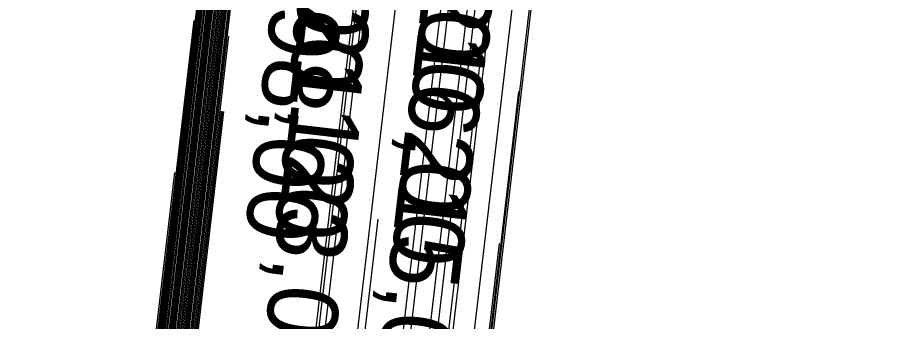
# Model space of a CAD drawing. Extents: x -500397 to -496810, y -1135552 to -1132176.
# Drawn here: x -500397.08 to -500372.54, y -1134717.01 to -1134708.35 of the extents above; entities that cross this region are included whole.
import ezdxf

# ---------------------------------------------------------------- set-up
doc = ezdxf.new("R2010")
doc.units = 0
doc.layers.add('30', color=7, linetype='Continuous')
doc.layers.add('40', color=7, linetype='Continuous')

msp = doc.modelspace()

# ---------------------------------------------------------------- linework, layer by layer
at = {"layer": '30'}
for points in [[(-500387.172, -1134737.454), (-500331.085, -1134256.995)], [(-500332.225, -1134267.69), (-500387.044, -1134737.277)], [(-500387.816, -1134738.339), (-500334.109, -1134278.277)], [(-500335.604, -1134301.879), (-500386.314, -1134736.273)], [(-500387.558, -1134737.985), (-500355.567, -1134463.937)], [(-500387.425, -1134728.512), (-500367.626, -1134558.908)], [(-500388.342, -1134738.221), (-500372.962, -1134606.474)], [(-500386.129, -1134660.947), (-500396.569, -1134750.38), (-500396.567, -1134750.485), (-500396.533, -1134750.568), (-500396.468, -1134750.631), (-500396.372, -1134750.671), (-500395.924, -1134750.792), (-500395.814, -1134750.827), (-500395.707, -1134750.87), (-500395.605, -1134750.921), (-500395.506, -1134750.981), (-500395.106, -1134751.248), (-500395.007, -1134751.313), (-500394.907, -1134751.376), (-500394.805, -1134751.438), (-500394.703, -1134751.498), (-500393.349, -1134752.284), (-500393.183, -1134752.384), (-500393.021, -1134752.487), (-500392.863, -1134752.596), (-500392.707, -1134752.709), (-500392.09, -1134753.172)], [(-500386.669, -1134665.264), (-500396.612, -1134750.439), (-500396.61, -1134750.539), (-500396.578, -1134750.619), (-500396.516, -1134750.678), (-500396.424, -1134750.717), (-500395.997, -1134750.832), (-500395.892, -1134750.864), (-500395.791, -1134750.905), (-500395.694, -1134750.954), (-500395.6, -1134751.012), (-500395.219, -1134751.265), (-500395.124, -1134751.327), (-500395.029, -1134751.388), (-500394.932, -1134751.447), (-500394.835, -1134751.504), (-500393.545, -1134752.253), (-500393.388, -1134752.347), (-500393.233, -1134752.446), (-500393.082, -1134752.55), (-500392.934, -1134752.657), (-500392.346, -1134753.098)], [(-500387.209, -1134669.582), (-500396.655, -1134750.499), (-500396.653, -1134750.593), (-500396.622, -1134750.669), (-500396.564, -1134750.725), (-500396.476, -1134750.762), (-500396.071, -1134750.871), (-500395.971, -1134750.902), (-500395.875, -1134750.941), (-500395.783, -1134750.988), (-500395.693, -1134751.042), (-500395.331, -1134751.283), (-500395.241, -1134751.342), (-500395.151, -1134751.399), (-500395.059, -1134751.455), (-500394.966, -1134751.51), (-500393.741, -1134752.221), (-500393.592, -1134752.311), (-500393.445, -1134752.405), (-500393.301, -1134752.503), (-500393.161, -1134752.606), (-500392.603, -1134753.024)], [(-500387.449, -1134672.562), (-500396.526, -1134750.321), (-500396.524, -1134750.431), (-500396.488, -1134750.518), (-500396.42, -1134750.583), (-500396.319, -1134750.626), (-500395.85, -1134750.753), (-500395.735, -1134750.789), (-500395.623, -1134750.834), (-500395.516, -1134750.888), (-500395.413, -1134750.951), (-500394.994, -1134751.23), (-500394.89, -1134751.298), (-500394.784, -1134751.364), (-500394.678, -1134751.429), (-500394.571, -1134751.493), (-500393.152, -1134752.316), (-500392.979, -1134752.42), (-500392.81, -1134752.529), (-500392.643, -1134752.643), (-500392.48, -1134752.761), (-500391.834, -1134753.246)], [(-500391.578, -1134753.32), (-500392.253, -1134752.813), (-500392.424, -1134752.689), (-500392.598, -1134752.57), (-500392.775, -1134752.456), (-500392.956, -1134752.348), (-500394.439, -1134751.487), (-500394.551, -1134751.421), (-500394.662, -1134751.353), (-500394.772, -1134751.283), (-500394.881, -1134751.212), (-500395.319, -1134750.92), (-500395.427, -1134750.855), (-500395.539, -1134750.798), (-500395.656, -1134750.751), (-500395.776, -1134750.713), (-500396.267, -1134750.581), (-500396.373, -1134750.536), (-500396.444, -1134750.468), (-500396.481, -1134750.377), (-500396.483, -1134750.262), (-500387.413, -1134672.566)], [(-500391.322, -1134753.394), (-500392.026, -1134752.865), (-500392.204, -1134752.735), (-500392.386, -1134752.611), (-500392.571, -1134752.493), (-500392.76, -1134752.379), (-500394.308, -1134751.481), (-500394.425, -1134751.412), (-500394.54, -1134751.341), (-500394.655, -1134751.269), (-500394.769, -1134751.194), (-500395.226, -1134750.89), (-500395.338, -1134750.821), (-500395.455, -1134750.762), (-500395.577, -1134750.713), (-500395.703, -1134750.674), (-500396.215, -1134750.536), (-500396.325, -1134750.489), (-500396.399, -1134750.418), (-500396.438, -1134750.323), (-500396.44, -1134750.203), (-500387.378, -1134672.57)], [(-500392.725, -1134753.047), (-500392.859, -1134752.95), (-500393.387, -1134752.554), (-500393.521, -1134752.457), (-500393.657, -1134752.364), (-500393.796, -1134752.275), (-500393.937, -1134752.19), (-500395.098, -1134751.516), (-500395.186, -1134751.464), (-500395.273, -1134751.411), (-500395.359, -1134751.356), (-500395.444, -1134751.301), (-500395.787, -1134751.072), (-500395.871, -1134751.021), (-500395.959, -1134750.977), (-500396.05, -1134750.94), (-500396.145, -1134750.91), (-500396.529, -1134750.807), (-500396.611, -1134750.772), (-500396.667, -1134750.719), (-500396.696, -1134750.647), (-500396.698, -1134750.558), (-500387.749, -1134673.9)], [(-500388.289, -1134678.218), (-500396.741, -1134750.617), (-500396.739, -1134750.701), (-500396.712, -1134750.769), (-500396.659, -1134750.819), (-500396.581, -1134750.852), (-500396.218, -1134750.95), (-500396.129, -1134750.978), (-500396.043, -1134751.013), (-500395.96, -1134751.054), (-500395.88, -1134751.103), (-500395.556, -1134751.318), (-500395.476, -1134751.371), (-500395.395, -1134751.423), (-500395.313, -1134751.473), (-500395.23, -1134751.522), (-500394.134, -1134752.158), (-500394, -1134752.238), (-500393.869, -1134752.322), (-500393.74, -1134752.41), (-500393.614, -1134752.502), (-500393.115, -1134752.876), (-500392.989, -1134752.968), (-500392.86, -1134753.056)], [(-500388.089, -1134678.972), (-500396.397, -1134750.144), (-500396.395, -1134750.269), (-500396.355, -1134750.368), (-500396.277, -1134750.442), (-500396.163, -1134750.491), (-500395.629, -1134750.634), (-500395.498, -1134750.675), (-500395.372, -1134750.727), (-500395.25, -1134750.788), (-500395.132, -1134750.859), (-500394.656, -1134751.177), (-500394.538, -1134751.254), (-500394.418, -1134751.33), (-500394.298, -1134751.403), (-500394.176, -1134751.475), (-500392.564, -1134752.411), (-500392.367, -1134752.529), (-500392.174, -1134752.653), (-500391.985, -1134752.782), (-500391.8, -1134752.917), (-500391.066, -1134753.468)], [(-500390.809, -1134753.542), (-500391.573, -1134752.969), (-500391.766, -1134752.828), (-500391.962, -1134752.694), (-500392.163, -1134752.565), (-500392.367, -1134752.443), (-500394.044, -1134751.469), (-500394.171, -1134751.395), (-500394.296, -1134751.318), (-500394.42, -1134751.239), (-500394.543, -1134751.159), (-500395.039, -1134750.829), (-500395.161, -1134750.755), (-500395.288, -1134750.691), (-500395.419, -1134750.638), (-500395.555, -1134750.595), (-500396.11, -1134750.445), (-500396.23, -1134750.395), (-500396.31, -1134750.318), (-500396.352, -1134750.215), (-500396.354, -1134750.085), (-500388.053, -1134678.976)], [(-500391.346, -1134753.021), (-500391.546, -1134752.875), (-500391.75, -1134752.735), (-500391.959, -1134752.602), (-500392.171, -1134752.474), (-500393.912, -1134751.464), (-500394.044, -1134751.386), (-500394.174, -1134751.306), (-500394.303, -1134751.225), (-500394.431, -1134751.141), (-500394.945, -1134750.799), (-500395.072, -1134750.721), (-500395.204, -1134750.655), (-500395.34, -1134750.6), (-500395.482, -1134750.556), (-500396.058, -1134750.4), (-500396.182, -1134750.348), (-500396.265, -1134750.268), (-500396.309, -1134750.161), (-500396.312, -1134750.026), (-500388.018, -1134678.98)], [(-500391.678, -1134743.652), (-500384.18, -1134679.428)], [(-500396.783, -1134750.676), (-500388.829, -1134682.536)], [(-500388.729, -1134685.381), (-500396.269, -1134749.967), (-500396.266, -1134750.107), (-500396.221, -1134750.218), (-500396.134, -1134750.301), (-500396.006, -1134750.355), (-500395.408, -1134750.516), (-500395.261, -1134750.562), (-500395.12, -1134750.619), (-500394.983, -1134750.688), (-500394.852, -1134750.768), (-500394.318, -1134751.123), (-500394.186, -1134751.21), (-500394.052, -1134751.295), (-500393.917, -1134751.377), (-500393.781, -1134751.458), (-500391.975, -1134752.506), (-500391.755, -1134752.638), (-500391.539, -1134752.777), (-500391.327, -1134752.921), (-500391.119, -1134753.072)], [(-500384.856, -1134685.834), (-500391.592, -1134743.533)], [(-500396.826, -1134750.735), (-500389.369, -1134686.853)], [(-500390.892, -1134753.124), (-500391.107, -1134752.968), (-500391.327, -1134752.818), (-500391.55, -1134752.674), (-500391.779, -1134752.538), (-500393.649, -1134751.452), (-500393.79, -1134751.369), (-500393.93, -1134751.283), (-500394.069, -1134751.195), (-500394.206, -1134751.106), (-500394.758, -1134750.738), (-500394.894, -1134750.655), (-500395.036, -1134750.584), (-500395.182, -1134750.524), (-500395.335, -1134750.477), (-500395.953, -1134750.31), (-500396.086, -1134750.254), (-500396.176, -1134750.168), (-500396.223, -1134750.053), (-500396.226, -1134749.908), (-500388.942, -1134687.518)], [(-500389.156, -1134689.655), (-500396.183, -1134749.849), (-500396.18, -1134749.999), (-500396.132, -1134750.118), (-500396.039, -1134750.206), (-500395.901, -1134750.265), (-500395.261, -1134750.437), (-500395.104, -1134750.487), (-500394.952, -1134750.548), (-500394.806, -1134750.622), (-500394.665, -1134750.707), (-500394.093, -1134751.088), (-500393.951, -1134751.181), (-500393.808, -1134751.272), (-500393.663, -1134751.36), (-500393.517, -1134751.446), (-500391.582, -1134752.569), (-500391.346, -1134752.711), (-500391.115, -1134752.859), (-500390.888, -1134753.014), (-500390.666, -1134753.176)], [(-500389.909, -1134691.171), (-500396.869, -1134750.794)], [(-500389.369, -1134691.791), (-500396.14, -1134749.79), (-500396.137, -1134749.945), (-500396.087, -1134750.068), (-500395.991, -1134750.159), (-500395.849, -1134750.22), (-500395.187, -1134750.398), (-500395.025, -1134750.449), (-500394.868, -1134750.512), (-500394.717, -1134750.588), (-500394.571, -1134750.677), (-500393.981, -1134751.07), (-500393.834, -1134751.166), (-500393.686, -1134751.26), (-500393.536, -1134751.351), (-500393.385, -1134751.441), (-500391.386, -1134752.601), (-500391.142, -1134752.747), (-500390.903, -1134752.901), (-500390.669, -1134753.061)], [(-500380.743, -1134693.182), (-500385.671, -1134735.388), (-500385.641, -1134736.758), (-500385.201, -1134737.849), (-500384.35, -1134738.663), (-500383.089, -1134739.197), (-500377.22, -1134740.779), (-500375.778, -1134741.23), (-500374.387, -1134741.793), (-500373.046, -1134742.468), (-500371.756, -1134743.254), (-500366.516, -1134746.742), (-500365.215, -1134747.594), (-500363.901, -1134748.426), (-500362.574, -1134749.237), (-500361.235, -1134750.028), (-500343.499, -1134760.322)], [(-500389.583, -1134693.928), (-500396.097, -1134749.731), (-500396.094, -1134749.891), (-500396.042, -1134750.018), (-500395.943, -1134750.112), (-500395.797, -1134750.174), (-500395.114, -1134750.358), (-500394.946, -1134750.411), (-500394.784, -1134750.476), (-500394.628, -1134750.555), (-500394.478, -1134750.646), (-500393.868, -1134751.052), (-500393.717, -1134751.152), (-500393.564, -1134751.248), (-500393.409, -1134751.343), (-500393.254, -1134751.435), (-500391.19, -1134752.633), (-500390.938, -1134752.784), (-500390.691, -1134752.942), (-500390.449, -1134753.107)], [(-500389.547, -1134693.932), (-500396.054, -1134749.672), (-500396.051, -1134749.837), (-500395.998, -1134749.968), (-500395.896, -1134750.065), (-500395.744, -1134750.129), (-500395.04, -1134750.319), (-500394.867, -1134750.373), (-500394.7, -1134750.441), (-500394.539, -1134750.522), (-500394.384, -1134750.616), (-500393.755, -1134751.035), (-500393.599, -1134751.137), (-500393.442, -1134751.237), (-500393.282, -1134751.334), (-500393.122, -1134751.429), (-500390.994, -1134752.664), (-500390.734, -1134752.82), (-500390.479, -1134752.983), (-500390.23, -1134753.154)], [(-500390.268, -1134753.024), (-500390.53, -1134752.856), (-500390.797, -1134752.696), (-500392.99, -1134751.423), (-500393.156, -1134751.325), (-500393.32, -1134751.225), (-500393.482, -1134751.122), (-500393.643, -1134751.017), (-500394.291, -1134750.586), (-500394.45, -1134750.488), (-500394.616, -1134750.405), (-500394.788, -1134750.335), (-500394.966, -1134750.28), (-500395.692, -1134750.084), (-500395.848, -1134750.018), (-500395.953, -1134749.917), (-500396.008, -1134749.783), (-500396.011, -1134749.613), (-500389.512, -1134693.936)], [(-500390.056, -1134753.066), (-500390.326, -1134752.893), (-500390.601, -1134752.727), (-500392.858, -1134751.417), (-500393.029, -1134751.317), (-500393.198, -1134751.213), (-500393.365, -1134751.108), (-500393.53, -1134750.999), (-500394.197, -1134750.555), (-500394.361, -1134750.455), (-500394.532, -1134750.369), (-500394.709, -1134750.298), (-500394.893, -1134750.24), (-500395.64, -1134750.039), (-500395.8, -1134749.971), (-500395.909, -1134749.867), (-500395.965, -1134749.728), (-500395.968, -1134749.554), (-500389.476, -1134693.94)], [(-500385.674, -1134694.384), (-500391.377, -1134743.238)], [(-500390.449, -1134695.489), (-500396.912, -1134750.853)], [(-500390.989, -1134699.807), (-500396.955, -1134750.912)], [(-500390.262, -1134741.704), (-500385.541, -1134701.266)], [(-500390.436, -1134702.474), (-500395.925, -1134749.495), (-500395.922, -1134749.674), (-500395.864, -1134749.817), (-500395.753, -1134749.924), (-500395.587, -1134749.994), (-500394.819, -1134750.201), (-500394.63, -1134750.26), (-500394.448, -1134750.334), (-500394.273, -1134750.422), (-500394.104, -1134750.525), (-500393.418, -1134750.981), (-500393.247, -1134751.093), (-500393.075, -1134751.202), (-500392.902, -1134751.308), (-500392.727, -1134751.412), (-500390.405, -1134752.759), (-500390.122, -1134752.929), (-500389.844, -1134753.107)], [(-500391.529, -1134704.124), (-500396.998, -1134750.971)], [(-500389.632, -1134753.148), (-500389.918, -1134752.965), (-500390.208, -1134752.791), (-500392.595, -1134751.406), (-500392.775, -1134751.299), (-500392.953, -1134751.19), (-500393.13, -1134751.078), (-500393.305, -1134750.964), (-500394.01, -1134750.494), (-500394.184, -1134750.389), (-500394.364, -1134750.298), (-500394.551, -1134750.222), (-500394.745, -1134750.161), (-500395.535, -1134749.949), (-500395.705, -1134749.877), (-500395.819, -1134749.767), (-500395.879, -1134749.62), (-500395.882, -1134749.436), (-500390.65, -1134704.611)], [(-500389.42, -1134753.19), (-500389.713, -1134753.002), (-500390.012, -1134752.822), (-500392.463, -1134751.4), (-500392.648, -1134751.291), (-500392.831, -1134751.179), (-500393.013, -1134751.064), (-500393.193, -1134750.946), (-500393.917, -1134750.464), (-500394.095, -1134750.355), (-500394.28, -1134750.262), (-500394.473, -1134750.184), (-500394.672, -1134750.122), (-500395.483, -1134749.903), (-500395.657, -1134749.83), (-500395.775, -1134749.717), (-500395.835, -1134749.566), (-500395.84, -1134749.377), (-500390.614, -1134704.615)], [(-500343.695, -1134760.29), (-500361.367, -1134750.034), (-500362.701, -1134749.246), (-500364.023, -1134748.437), (-500365.332, -1134747.609), (-500366.628, -1134746.76), (-500371.849, -1134743.284), (-500373.135, -1134742.501), (-500374.471, -1134741.829), (-500375.857, -1134741.268), (-500377.294, -1134740.818), (-500383.141, -1134739.242), (-500384.398, -1134738.71), (-500385.246, -1134737.9), (-500385.684, -1134736.812), (-500385.713, -1134735.447), (-500382.293, -1134706.144)], [(-500392.069, -1134708.442), (-500397.041, -1134751.03)], [(-500391.076, -1134708.884), (-500395.797, -1134749.318), (-500395.792, -1134749.512), (-500395.73, -1134749.667), (-500395.609, -1134749.782), (-500395.43, -1134749.858), (-500394.598, -1134750.083), (-500394.394, -1134750.147), (-500394.196, -1134750.226), (-500394.006, -1134750.322), (-500393.823, -1134750.434), (-500393.08, -1134750.928), (-500392.896, -1134751.049), (-500392.709, -1134751.167), (-500392.521, -1134751.282), (-500392.331, -1134751.394), (-500389.816, -1134752.854), (-500389.509, -1134753.038)], [(-500382.833, -1134710.461), (-500385.756, -1134735.506), (-500385.727, -1134736.866), (-500385.29, -1134737.95), (-500384.446, -1134738.757), (-500383.193, -1134739.288), (-500377.367, -1134740.858), (-500375.936, -1134741.306), (-500374.555, -1134741.865), (-500373.224, -1134742.534), (-500371.943, -1134743.315), (-500366.741, -1134746.778), (-500365.449, -1134747.623), (-500364.145, -1134748.449), (-500362.828, -1134749.254), (-500361.498, -1134750.04), (-500343.892, -1134760.258)], [(-500391.29, -1134711.021), (-500395.754, -1134749.259), (-500395.749, -1134749.458), (-500395.685, -1134749.617), (-500395.562, -1134749.735), (-500395.378, -1134749.813), (-500394.525, -1134750.043), (-500394.315, -1134750.109), (-500394.112, -1134750.191), (-500393.917, -1134750.289), (-500393.73, -1134750.403), (-500392.968, -1134750.91), (-500392.778, -1134751.034), (-500392.587, -1134751.155), (-500392.394, -1134751.273), (-500392.199, -1134751.388), (-500389.62, -1134752.886), (-500389.305, -1134753.074)], [(-500389.101, -1134753.111), (-500389.423, -1134752.917), (-500392.068, -1134751.383), (-500392.267, -1134751.265), (-500392.465, -1134751.144), (-500392.661, -1134751.02), (-500392.855, -1134750.893), (-500393.636, -1134750.373), (-500393.829, -1134750.255), (-500394.028, -1134750.155), (-500394.236, -1134750.071), (-500394.451, -1134750.004), (-500395.326, -1134749.768), (-500395.514, -1134749.688), (-500395.641, -1134749.567), (-500395.706, -1134749.404), (-500395.711, -1134749.2), (-500391.254, -1134711.025)], [(-500391.219, -1134711.029), (-500395.668, -1134749.141), (-500395.663, -1134749.35), (-500395.596, -1134749.517), (-500395.466, -1134749.641), (-500395.274, -1134749.723), (-500394.377, -1134749.964), (-500394.157, -1134750.033), (-500393.945, -1134750.119), (-500393.74, -1134750.222), (-500393.543, -1134750.342), (-500392.742, -1134750.875), (-500392.544, -1134751.005), (-500392.343, -1134751.132), (-500392.14, -1134751.256), (-500391.936, -1134751.377), (-500389.227, -1134752.949), (-500388.897, -1134753.147)], [(-500397.084, -1134751.089), (-500392.609, -1134712.76)], [(-500390.004, -1134741.349), (-500386.821, -1134714.086)], [(-500344.088, -1134760.227), (-500361.63, -1134750.045), (-500362.955, -1134749.263), (-500364.267, -1134748.46), (-500365.566, -1134747.638), (-500366.853, -1134746.795), (-500372.036, -1134743.345), (-500373.312, -1134742.567), (-500374.638, -1134741.9), (-500376.015, -1134741.343), (-500377.441, -1134740.897), (-500383.245, -1134739.333), (-500384.493, -1134738.804), (-500385.335, -1134738), (-500385.77, -1134736.92), (-500385.799, -1134735.565), (-500383.373, -1134714.779)]]:
    msp.add_lwpolyline(points, dxfattribs=at)

# ---------------------------------------------------------------- texts
at = {"layer": '40'}
for s, p in [('119,00', (-500388.417, -1134702.157)), ('217,00', (-500384.968, -1134702.851)), ('121,00', (-500388.843, -1134706.43)), ('216,00', (-500385.508, -1134707.169)), ('98,00', (-500389.849, -1134707.945)), ('123,00', (-500389.27, -1134710.704)), ('215,00', (-500386.048, -1134711.486))]:
    msp.add_text(s, height=2, rotation=263.3416, dxfattribs=at).set_placement(p)

doc.saveas('drawing.dxf')
